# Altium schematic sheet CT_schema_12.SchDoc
size 390 x 278 mm
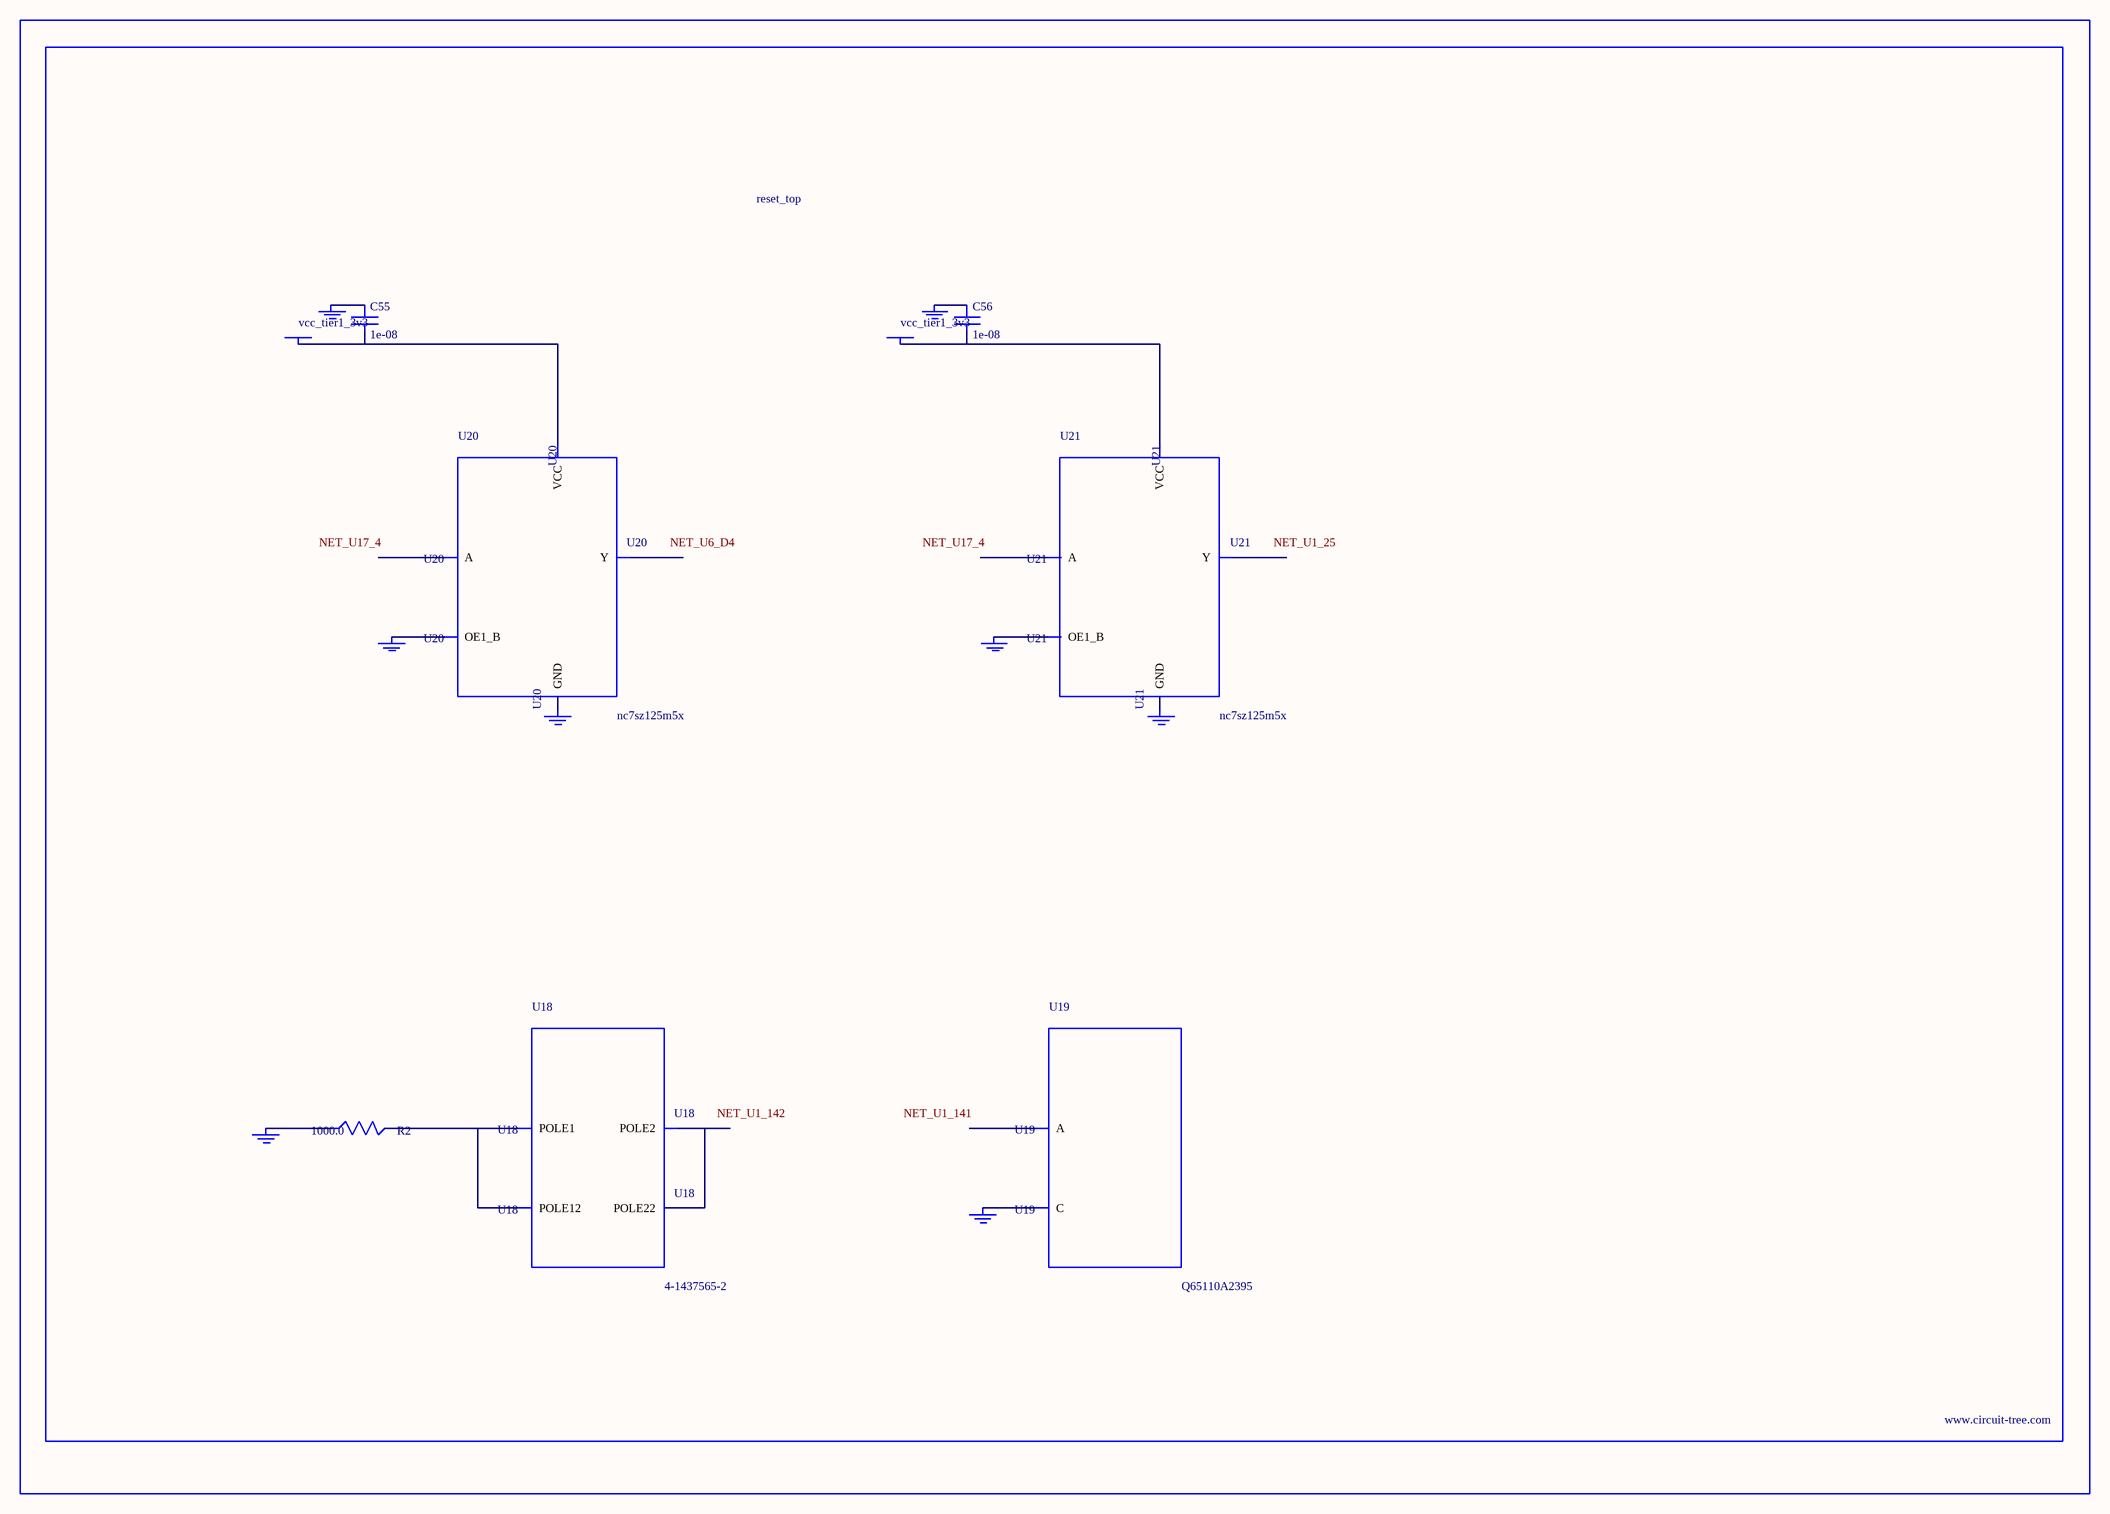
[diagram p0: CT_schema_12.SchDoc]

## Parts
BORDER11  (no value)
C55  1e-08  [C0402]
C56  1e-08  [C0402]
GND_INSTANCE_11_0  (no value)
GND_INSTANCE_11_1  (no value)
GND_INSTANCE_11_2  (no value)
GND_INSTANCE_11_3  (no value)
GND_INSTANCE_11_4  (no value)
GND_INSTANCE_11_5  (no value)
GND_INSTANCE_11_6  (no value)
GND_INSTANCE_11_7  (no value)
POWER_INSTANCE_11_0  vcc_tier1_3v3
POWER_INSTANCE_11_1  vcc_tier1_3v3
R2  1000.0  [R0603]
U18  4-1437565-2  [SW_4-1437565-2]
U19  Q65110A2395  [LGM67K-G1J2-24-Z]
U20  nc7sz125m5x  [NC7SZ125M5X]
U21  nc7sz125m5x  [NC7SZ125M5X]

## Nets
NetC55_1: C55.1 GND_INSTANCE_11_2.0(GND)
NetC55_2: C55.2 POWER_INSTANCE_11_0.0(PWR) U20.5(VCC)
NetC56_1: C56.1 GND_INSTANCE_11_5.0(GND)
NetC56_2: C56.2 POWER_INSTANCE_11_1.0(PWR) U21.5(VCC)
NetGND_INSTANCE_11_0_0: GND_INSTANCE_11_0.0(GND) R2.1
NetGND_INSTANCE_11_1_0: GND_INSTANCE_11_1.0(GND) U19.C
NetGND_INSTANCE_11_3_0: GND_INSTANCE_11_3.0(GND) U20.1(OE1_B)
NetGND_INSTANCE_11_4_0: GND_INSTANCE_11_4.0(GND) U20.3(GND)
NetGND_INSTANCE_11_6_0: GND_INSTANCE_11_6.0(GND) U21.1(OE1_B)
NetGND_INSTANCE_11_7_0: GND_INSTANCE_11_7.0(GND) U21.3(GND)
NetR2_2: R2.2 U18.1(POLE1) U18.2(POLE12)
NetU18_3: U18.3(POLE2) U18.4(POLE22)

Not connected (* = marked no-connect by the designer): U19 A; U20 2(A) 4(Y); U21 2(A) 4(Y)

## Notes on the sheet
- Labels drawn without touching a wire or pin: NET_U1_25, NET_U1_141, NET_U1_142, NET_U6_D4, NET_U17_4

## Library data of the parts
BORDER11 = BORDER_PAGE11
C55 C56 = C0402C103K3RAC
GND_INSTANCE_11_0-GND_INSTANCE_11_7 = GND
POWER_INSTANCE_11_0 POWER_INSTANCE_11_1 = PWR
R2 = RC0603JR-071KL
